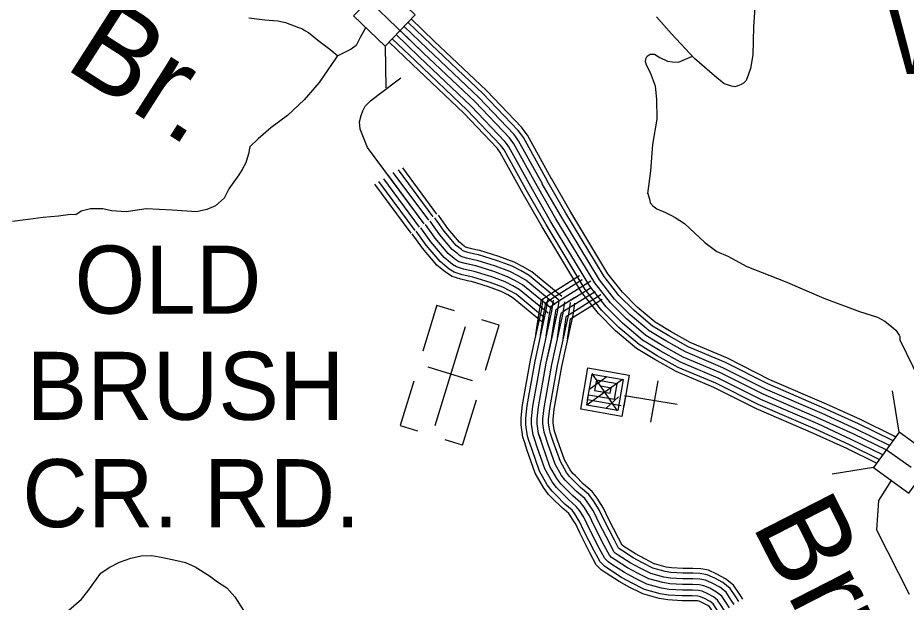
# Model space of a CAD drawing. Extents: x 1551132 to 1791609, y 378168 to 563823.
# Drawn here: x 1684674 to 1689511, y 423787 to 426966 of the extents above; entities that cross this region are included whole.
import ezdxf

# ---------------------------------------------------------------- set-up
doc = ezdxf.new("R2010")
doc.units = 0
for name, color, linetype in [('DESIGN - DRAINAGE - Bridges and Cross Drains Size Text', 7, 'Continuous'), ('DESIGN - ROW - Right-of-Way and Easement Labels', 7, 'Continuous'), ('DESIGN - TRANSPORTATION - Text', 7, 'Continuous'), ('DESIGN - UTILITIES - Cable (Underground) with Text', 7, 'Continuous'), ('SURVEY - CONTOURS - Index with Text', 7, 'Continuous'), ('SURVEY - DRAINAGE - Storm Sewer', 7, 'Continuous'), ('SURVEY - PROPERTY - Owners', 7, 'Continuous'), ('SURVEY - TRANSPORTATION - Roads', 7, 'Continuous')]:
    doc.layers.add(name, color=color, linetype=linetype)

msp = doc.modelspace()

# ---------------------------------------------------------------- linework, layer by layer
at = {"layer": 'DESIGN - TRANSPORTATION - Text'}
for points in [[(1688693.47, 427129.736), (1688679.112, 426917.664), (1688675.42, 426765.535), (1688662.579, 426689.599), (1688652.246, 426659.69), (1688639.863, 426625.798), (1688625.688, 426609.947), (1688611.622, 426604.106), (1688593.53, 426596.314), (1688591.505, 426594.339), (1688577.464, 426590.497), (1688559.506, 426594.714), (1688543.557, 426598.914), (1688519.64, 426607.206), (1688468.108, 426649.865), (1688359.161, 426745.259), (1688232.631, 426878.913), (1688151.658, 426971.982)], [(1685931.326, 426966.297), (1686019.216, 426955.239), (1686089.173, 426950.405), (1686131.055, 426939.896), (1686202.77, 426913.012), (1686220.719, 426908.796), (1686236.586, 426896.595), (1686256.477, 426886.345), (1686313.967, 426839.611), (1686373.474, 426794.859), (1686416.29, 426759.917)], [(1686567.728, 426912.863), (1686564.761, 426908.721), (1686538.204, 426858.978), (1686515.721, 426815.193), (1686489.496, 426795.485), (1686445.247, 426773.984), (1686413.073, 426758.35), (1686400.873, 426740.475), (1686362.224, 426682.865), (1686315.45, 426613.338), (1686232.402, 426520.219), (1686141.446, 426435.2), (1686050.69, 426368.198), (1685982, 426306.946)], [(1688104.158, 426008.531), (1688120.325, 426133.401), (1688131.933, 426277.422), (1688155.466, 426415.3), (1688152.666, 426523.462), (1688145.449, 426593.622), (1688118.25, 426666.032), (1688098.675, 426704.3), (1688090.917, 426726.417), (1688093.092, 426742.409), (1688101.275, 426758.334), (1688117.383, 426768.151), (1688141.383, 426767.868), (1688169.182, 426749.517), (1688210.981, 426731), (1688238.939, 426726.667), (1688270.913, 426724.284), (1688348.236, 426756.801)], [(1685982, 426306.946), (1685937.517, 426263.42), (1685929.093, 426225.478), (1685914.56, 426177.601), (1685896.16, 426141.775), (1685877.827, 426111.958), (1685823.187, 426036.256)], [(1685823.187, 426036.256), (1685796.571, 425984.513), (1685749.638, 425942.937), (1685702.464, 425924.061), (1685645.849, 425909.903), (1685513.769, 425919.344), (1685372.247, 425926.411), (1685263.75, 425909.902), (1685183.552, 425916.978), (1685136.378, 425926.411), (1685070.338, 425926.411), (1685018.439, 425914.627), (1684989.248, 425894.352), (1684961.265, 425896.702), (1684895.133, 425887.502), (1684811.027, 425880.535), (1684730.871, 425869.509), (1684644.714, 425858.559)], [(1688103.658, 426010.098), (1688113.308, 425979.939), (1688117.075, 425959.863), (1688130.891, 425943.671), (1688152.707, 425927.379), (1688200.481, 425906.77), (1688230.33, 425892.378), (1688252.188, 425880.095), (1688303.828, 425847.411), (1688414.659, 425743.908), (1688480.116, 425695.04), (1688539.848, 425670.273), (1688643.212, 425612.921), (1688852.349, 425532.236), (1689063.36, 425441.517), (1689256.581, 425369.04), (1689354.254, 425337.789), (1689394.003, 425315.272), (1689433.66, 425284.746), (1689455.46, 425266.454), (1689473.159, 425240.195), (1689477.067, 425232.137), (1689476.859, 425214.119), (1689585.573, 424991.18)], [(1689430.693, 424449.016), (1689429.168, 424450.258), (1689360.153, 424340.438), (1689349.728, 424181.092), (1689528.007, 423831.925)], [(1684952.198, 423743.995), (1685020.913, 423803.23), (1685055.429, 423846.856), (1685126.61, 423946.109), (1685170.968, 423975.602), (1685227.333, 424004.944), (1685289.598, 424026.203), (1685345.772, 424039.528), (1685403.812, 424040.82), (1685463.702, 424030.061), (1685539.559, 424015.111), (1685587.425, 424002.502), (1685639.182, 423979.835), (1685716.638, 423930.817), (1685760.27, 423898.233), (1685811.911, 423865.557), (1685855.36, 423816.956), (1685902.5, 423742.279)]]:
    msp.add_lwpolyline(points, dxfattribs=at)
at = {"layer": 'DESIGN - UTILITIES - Cable (Underground) with Text'}
for p, q in [((1686955.396, 425402.2), (1686879.234, 425152.669)), ((1687050.79, 425372.985), (1686956.013, 425402.025)), ((1687295.171, 425294.188), (1687199.735, 425323.27)), ((1687220.066, 425048.658), (1687295.087, 425294.138)), ((1687150.374, 424992.114), (1686907.836, 425066.21)), ((1686829.253, 424989.166), (1686755.731, 424748.702)), ((1688121.11, 424767.269), (1688160.665, 424992.015)), ((1687095.289, 424640.774), (1687170.702, 424887.704)), ((1686755.915, 424748.702), (1686849.85, 424719.92)), ((1687095.156, 424640.815), (1686999.987, 424669.856))]:
    msp.add_line(p, q, dxfattribs=at)
for points in [[(1687108.826, 425284.768), (1686944.234, 424746.372)], [(1687987.97, 424908.682), (1687983.087, 424909.648), (1687963.105, 424797.184), (1687738.534, 424836.78), (1687778.264, 425061.485), (1688002.835, 425021.888), (1687973.096, 424853.374), (1687969.137, 424854.249)], [(1687959.146, 424855.924), (1687776.599, 424887.996), (1687801.364, 425028.527), (1687969.836, 424998.655), (1687940.055, 424830.274), (1687771.708, 424859.88), (1687781.524, 424916.071), (1687921.88, 424891.39), (1687936.753, 424975.555), (1687824.506, 424995.403), (1687814.431, 424939.254), (1687898.696, 424924.43), (1687903.704, 424952.505), (1687847.522, 424962.446)], [(1687966.761, 424998.53), (1687773.825, 424860.805)], [(1687880.604, 425013.662), (1687788.999, 424946.954)], [(1687939.788, 424828.558), (1687800.664, 425030.644)], [(1687944.321, 424904.765), (1687877.131, 424842.457)], [(1688263.581, 424862.527), (1687977.278, 424910.532)]]:
    msp.add_lwpolyline(points, dxfattribs=at)
at = {"layer": 'SURVEY - CONTOURS - Index with Text'}
for points in [[(1687502.781, 426047.807), (1687374.109, 426280.796), (1687359.976, 426300.164), (1687350.301, 426313.564), (1687163.505, 426508.177), (1686881.071, 426776.409), (1686594.669, 427050.675), (1686288.393, 427345.099), (1686103.389, 427516.553), (1685954.168, 427649.723), (1685854.595, 427724.475), (1685673.141, 427821.803), (1685535.428, 427874.787), (1685401.639, 427915.722), (1685253.759, 427942.722), (1684941.967, 427992.84), (1684604.15, 428039.116), (1683694.396, 428125.201), (1683124.384, 428152.977), (1682908.423, 428170.419), (1682708.627, 428213.787), (1682458.833, 428259.488), (1682121.15, 428327.798)], [(1687557.054, 426077.783), (1687426.491, 426314.189), (1687410.15, 426336.59), (1687398.033, 426353.373), (1687207.238, 426552.145), (1686923.861, 426821.277), (1686798.514, 426941.314)], [(1687579.562, 426090.217), (1687448.224, 426328.039), (1687430.957, 426351.69), (1687417.824, 426369.882), (1687225.379, 426570.387), (1686941.603, 426839.894), (1686816.381, 426959.814)], [(1687475.648, 426032.823), (1687347.918, 426264.096), (1687334.893, 426281.955), (1687326.435, 426293.663), (1687141.639, 426486.193), (1686859.679, 426753.975), (1686733.916, 426874.412)], [(1687502.781, 426047.807), (1687374.109, 426280.796), (1687359.976, 426300.164), (1687350.301, 426313.564), (1687163.505, 426508.177), (1686881.071, 426776.409), (1686755.457, 426896.704)], [(1687529.913, 426062.791), (1687400.3, 426297.497), (1687385.059, 426318.372), (1687374.167, 426333.465), (1687185.372, 426530.161), (1686902.462, 426798.843), (1686776.973, 426919.013)], [(1687426.874, 426005.881), (1687300.844, 426234.087), (1687289.802, 426249.221), (1687283.544, 426257.887), (1687102.34, 426446.676), (1686821.23, 426713.649), (1686695.2, 426834.344)], [(1687448.507, 426017.831), (1687321.727, 426247.404), (1687309.802, 426263.738), (1687302.569, 426273.755), (1687119.773, 426464.209), (1686838.28, 426731.541), (1686712.375, 426852.111)], [(1689420.035, 424639.996), (1689416.793, 424642.246), (1689238.581, 424729.265), (1689054.135, 424813.442), (1688745.001, 424946.362), (1688513.307, 425062.79), (1688310.128, 425148.592), (1688202.356, 425208.635), (1688111.174, 425264.045), (1688008.493, 425350.831), (1687923.312, 425435.558), (1687840.389, 425541.586), (1687630.153, 425888.311), (1687529.663, 426063.249)], [(1689438.276, 424665.063), (1689432.518, 424669.063), (1689251.814, 424757.299), (1689066.693, 424841.793), (1688758.092, 424974.471), (1688526.315, 425090.949), (1688323.736, 425176.501), (1688217.955, 425235.428), (1688129.341, 425289.287), (1688029.468, 425373.698), (1687946.537, 425456.175), (1687865.947, 425559.228), (1687656.844, 425904.07), (1687556.538, 426078.691)], [(1689453.376, 424685.889), (1689445.568, 424691.314), (1689262.797, 424780.558), (1689077.11, 424865.302), (1688768.959, 424997.797), (1688537.098, 425114.316), (1688335.027, 425199.644), (1688230.888, 425257.662), (1688144.407, 425310.221), (1688046.859, 425392.665), (1687965.811, 425473.284), (1687887.138, 425573.87), (1687678.993, 425917.145), (1687578.837, 426091.5)], [(1689350.02, 424543.852), (1689188.307, 424622.812), (1689006.445, 424705.814), (1688695.285, 424839.601), (1688463.933, 424955.854), (1688258.429, 425042.639), (1688143.124, 425106.874), (1688042.193, 425168.218), (1687928.87, 425263.995), (1687835.098, 425357.264), (1687743.358, 425474.567), (1687528.772, 425828.468), (1687427.591, 426004.614)], [(1689364.536, 424564.269), (1689198.865, 424645.163), (1689016.461, 424728.407), (1688705.727, 424862.018), (1688474.299, 424978.313), (1688269.287, 425064.882), (1688155.557, 425128.242), (1688056.676, 425188.335), (1687945.587, 425282.229), (1687853.622, 425373.706), (1687763.733, 425488.643), (1687550.063, 425841.035), (1687449.024, 426016.923)], [(1689383.361, 424589.57), (1689212.098, 424673.197), (1689029.019, 424756.757), (1688718.818, 424890.127), (1688487.307, 425006.472), (1688282.895, 425092.791), (1688171.156, 425155.034), (1688074.842, 425213.577), (1687966.561, 425305.096), (1687876.847, 425394.323), (1687789.29, 425506.285), (1687576.754, 425856.794), (1687475.898, 426032.365)], [(1689538.574, 424519.968), (1689401.061, 424615.429), (1689225.34, 424701.231), (1689041.577, 424785.1), (1688731.91, 424918.245), (1688500.307, 425034.631), (1688296.512, 425120.691), (1688186.756, 425181.835), (1688093.008, 425238.811), (1687987.527, 425327.963), (1687900.079, 425414.941), (1687814.84, 425523.935), (1687603.453, 425872.553), (1687502.781, 426047.807)], [(1689401.81, 424614.912), (1689401.061, 424615.429), (1689225.34, 424701.231), (1689041.577, 424785.1), (1688731.91, 424918.245), (1688500.307, 425034.631), (1688296.512, 425120.691), (1688186.756, 425181.835), (1688093.008, 425238.811), (1687987.527, 425327.963), (1687900.079, 425414.941), (1687814.84, 425523.935), (1687603.453, 425872.553), (1687502.781, 426047.807)]]:
    msp.add_lwpolyline(points, dxfattribs=at)
at = {"layer": 'SURVEY - DRAINAGE - Storm Sewer'}
for p, q in [((1686673.13, 426811.539), (1686677.094, 426584.455)), ((1689472.637, 424712.36), (1689437.107, 424936.701)), ((1689332.983, 424520.139), (1689108.659, 424484.559))]:
    msp.add_line(p, q, dxfattribs=at)
for points in [[(1686502.242, 426976.552), (1686673.163, 426811.497), (1686838.226, 426982.435), (1686667.28, 427147.49)], [(1689525.196, 424380.486), (1689664.858, 424572.698), (1689472.637, 424712.36), (1689332.983, 424520.139)]]:
    msp.add_lwpolyline(points, close=True, dxfattribs=at)
at = {"layer": 'SURVEY - PROPERTY - Owners'}
msp.add_lwpolyline([(1688532.372, 423781.748), (1688506.764, 423820.107), (1688478.982, 423842.466), (1688441.166, 423862.934), (1688409.292, 423877.334), (1688383.317, 423881.642), (1688347.751, 423883.217), (1688293.761, 423883.217), (1688223.238, 423887.517), (1688185.272, 423893.968), (1688109.032, 423914.485), (1688047.234, 423945.769), (1687992.843, 423975.061), (1687925.72, 424018.246), (1687907.254, 424031.038), (1687894.612, 424043.588), (1687867.155, 424095.989), (1687812.248, 424202.792), (1687786.815, 424257.177), (1687757.282, 424303.586), (1687737.549, 424329.862), (1687695.175, 424366.138), (1687648.36, 424413.031), (1687630.544, 424431.265), (1687608.827, 424459.557), (1687571.503, 424526.101), (1687530.704, 424640.754), (1687509.622, 424705.33), (1687501.93, 424757.265), (1687502.23, 424785.307), (1687508.922, 424849.326), (1687551.512, 425087.199), (1687612.553, 425364.914), (1687621.428, 425425.807)], dxfattribs=at)
at = {"layer": 'SURVEY - TRANSPORTATION - Roads'}
for points in [[(1686886.47, 425846.268), (1686578.644, 426261.029), (1686537.753, 426359.556), (1686534.195, 426399.616), (1686542.57, 426435.542), (1686552.82, 426459.442), (1686565.086, 426485.318), (1686593.377, 426515.011), (1686633.66, 426544.57), (1686759.282, 426640.472)], [(1686956.102, 425897.953), (1686769.34, 426149.593)], [(1686886.47, 425846.268), (1686691.8, 426108.567)], [(1686911.361, 425864.744), (1686718.016, 426125.259)], [(1686936.252, 425883.219), (1686746.732, 426138.576)], [(1686816.038, 425793.992), (1686617.543, 426061.44)], [(1686836.688, 425809.317), (1686638.643, 426076.157)], [(1686861.579, 425827.793), (1686666.825, 426090.199)], [(1687155.647, 425650.421), (1687116.981, 425658.888), (1687088.349, 425667.68), (1687077.54, 425674.605), (1687069.107, 425681.522), (1687039.441, 425706.198), (1686970.876, 425786.117), (1686918.453, 425859.71)], [(1687162.28, 425680.706), (1687124.864, 425688.897), (1687101.498, 425696.064), (1687095.798, 425699.723), (1687088.849, 425705.423), (1687061.274, 425728.365), (1686995.317, 425805.242), (1686943.702, 425877.702)], [(1687167.572, 425704.848), (1687131.139, 425712.831), (1687111.99, 425718.707), (1687110.356, 425719.757), (1687104.59, 425724.482), (1687078.674, 425746.032), (1687014.8, 425820.493), (1686963.827, 425892.044)], [(1687142.381, 425589.853), (1687101.232, 425598.87), (1687062.032, 425610.895), (1687041.025, 425624.371), (1687029.625, 425633.721), (1686995.792, 425661.863), (1686922.011, 425747.866), (1686867.954, 425823.743)], [(1687580.895, 425382.998), (1687422.149, 425513.051), (1687383.692, 425535.902), (1687340.559, 425558.069), (1687265.253, 425585.995), (1687167.022, 425616.187), (1687109.106, 425628.879), (1687075.19, 425639.288), (1687059.283, 425649.488), (1687049.366, 425657.622), (1687017.617, 425684.031), (1686946.444, 425766.991), (1686893.203, 425841.726)], [(1687149.014, 425620.137), (1687109.106, 425628.879), (1687075.19, 425639.288), (1687059.283, 425649.488), (1687049.366, 425657.622), (1687017.617, 425684.031), (1686946.444, 425766.991), (1686893.203, 425841.726)], [(1687130.247, 425534.452), (1687086.815, 425543.96), (1687037.966, 425558.952), (1687007.625, 425578.411), (1686993.509, 425589.986), (1686955.852, 425621.312), (1686877.295, 425712.873), (1686821.763, 425790.825)], [(1687135.747, 425559.569), (1687093.348, 425568.861), (1687048.883, 425582.511), (1687022.767, 425599.253), (1687009.884, 425609.82), (1686973.96, 425639.696), (1686897.57, 425728.74), (1686842.704, 425805.75)], [(1687620.186, 425430.958), (1687457.831, 425563.969), (1687413.724, 425590.178), (1687365.592, 425614.912), (1687285.152, 425644.738), (1687182.788, 425676.206), (1687162.272, 425680.706)], [(1687635.844, 425450.083), (1687472.056, 425584.27), (1687425.699, 425611.812), (1687375.575, 425637.571), (1687293.085, 425668.164), (1687189.08, 425700.131), (1687167.563, 425704.848)], [(1687580.895, 425382.998), (1687422.149, 425513.051), (1687383.692, 425535.902), (1687340.559, 425558.069), (1687265.253, 425585.995), (1687167.022, 425616.187), (1687148.997, 425620.137)], [(1687600.536, 425406.982), (1687439.99, 425538.51), (1687398.708, 425563.036), (1687353.076, 425586.487), (1687275.202, 425615.371), (1687174.905, 425646.196), (1687155.63, 425650.421)], [(1687561.254, 425359.014), (1687404.308, 425487.592), (1687368.675, 425508.768), (1687328.043, 425529.652), (1687255.303, 425556.619), (1687159.138, 425586.178), (1687142.364, 425589.853)], [(1687525.313, 425315.138), (1687371.667, 425441.008), (1687341.201, 425459.117), (1687305.135, 425477.65), (1687237.095, 425502.884), (1687144.714, 425531.277), (1687130.222, 425534.452)], [(1687541.604, 425335.038), (1687386.466, 425462.133), (1687353.659, 425481.625), (1687315.526, 425501.226), (1687245.353, 425527.252), (1687151.255, 425556.169), (1687135.722, 425559.569)], [(1687495.047, 425243.553), (1687512.43, 425362.856), (1687526.013, 425431.249), (1687578.837, 425468.792), (1687731.658, 425563.769)], [(1687520.497, 425239.844), (1687537.78, 425358.497), (1687549.246, 425416.216), (1687593.078, 425447.375), (1687747.1, 425543.077)], [(1687551.171, 425235.369), (1687568.345, 425353.239), (1687577.245, 425398.082), (1687610.261, 425421.549), (1687794.507, 425536.052)], [(1687581.845, 425230.902), (1687598.903, 425347.98), (1687605.253, 425379.956), (1687627.436, 425395.723), (1687794.907, 425499.801)], [(1687612.519, 425226.436), (1687629.461, 425342.722), (1687633.261, 425361.831), (1687644.61, 425369.898), (1687817.998, 425477.651)], [(1687485.864, 425197.11), (1687526.205, 425380.673), (1687534.63, 425438.458)], [(1688532.372, 423781.748), (1688506.764, 423820.107), (1688478.982, 423842.466), (1688441.166, 423862.934), (1688409.292, 423877.334), (1688383.317, 423881.642), (1688347.751, 423883.217), (1688293.761, 423883.217), (1688223.238, 423887.517), (1688185.272, 423893.968), (1688109.032, 423914.485), (1688047.234, 423945.769), (1687992.843, 423975.061), (1687925.72, 424018.246), (1687907.254, 424031.038), (1687894.612, 424043.588), (1687867.155, 424095.989), (1687812.248, 424202.792), (1687786.815, 424257.177), (1687757.282, 424303.586), (1687737.549, 424329.862), (1687695.175, 424366.138), (1687648.36, 424413.031), (1687630.544, 424431.265), (1687608.827, 424459.557), (1687571.503, 424526.101), (1687530.704, 424640.754), (1687509.622, 424705.33), (1687501.93, 424757.265), (1687502.23, 424785.307), (1687508.922, 424849.326), (1687551.512, 425087.199), (1687612.553, 425364.914), (1687621.428, 425425.807)], [(1687510.98, 425191.593), (1687551.521, 425376.056), (1687560.079, 425434.749)], [(1687541.263, 425184.943), (1687582.037, 425370.481), (1687590.753, 425430.283)], [(1687571.537, 425178.284), (1687612.553, 425364.914), (1687621.428, 425425.807)], [(1687581.845, 425230.902), (1687598.903, 425347.98), (1687605.253, 425379.956), (1687627.436, 425395.723), (1687705.426, 425444.191)], [(1687601.811, 425171.626), (1687643.069, 425359.347), (1687652.102, 425421.332)], [(1687643.194, 425221.96), (1687660.027, 425337.464), (1687661.26, 425343.697), (1687661.793, 425344.072), (1687848.839, 425460.333)], [(1687667.651, 425218.402), (1687683.709, 425328.597), (1687855.889, 425435.616)], [(1687632.094, 425164.976), (1687673.585, 425353.772), (1687682.776, 425416.866)], [(1687656.227, 425159.667), (1687697.909, 425349.331), (1687707.234, 425413.299)], [(1687432.498, 424658.937), (1687423.94, 424685.146), (1687414.149, 424751.273), (1687414.565, 424790.349), (1687422.015, 424861.634), (1687465.473, 425104.349), (1687485.864, 425197.135)], [(1687456.939, 424666.921), (1687449.056, 424691.063), (1687439.882, 424753.031), (1687440.265, 424788.866), (1687447.498, 424858.026), (1687490.697, 425099.324), (1687510.98, 425191.61)], [(1687486.414, 424676.538), (1687479.339, 424698.197), (1687470.906, 424755.148), (1687471.247, 424787.091), (1687478.206, 424853.676), (1687521.105, 425093.257), (1687541.263, 425184.959)], [(1687515.88, 424686.163), (1687509.622, 424705.33), (1687501.93, 424757.265), (1687502.23, 424785.307), (1687508.922, 424849.326), (1687551.512, 425087.199), (1687571.537, 425178.301)], [(1687545.346, 424695.788), (1687539.904, 424712.464), (1687532.954, 424759.382), (1687533.213, 424783.524), (1687539.638, 424844.976), (1687581.92, 425081.14), (1687601.811, 425171.642)], [(1687574.82, 424705.405), (1687570.187, 424719.597), (1687563.979, 424761.498), (1687564.195, 424781.749), (1687570.345, 424840.625), (1687612.328, 425075.073), (1687632.094, 425164.992)], [(1687598.311, 424713.08), (1687594.328, 424725.281), (1687588.711, 424763.19), (1687588.895, 424780.324), (1687594.836, 424837.159), (1687636.569, 425070.24), (1687656.227, 425159.684)], [(1687803.923, 424288.028), (1687782.79, 424321.245), (1687760.29, 424351.196), (1687716.258, 424388.897), (1687670.418, 424434.815), (1687654.01, 424451.607), (1687634.777, 424476.666), (1687599.828, 424538.976), (1687560.045, 424650.762), (1687545.337, 424695.805)], [(1687830.08, 424304.67), (1687808.298, 424338.904), (1687783.04, 424372.538), (1687737.333, 424411.664), (1687692.467, 424456.599), (1687677.476, 424471.949), (1687660.718, 424493.775), (1687628.152, 424551.843), (1687589.386, 424660.771), (1687574.803, 424705.422)], [(1687850.93, 424317.945), (1687828.639, 424352.979), (1687801.173, 424389.547), (1687754.141, 424429.806), (1687710.058, 424473.974), (1687696.184, 424488.175), (1687681.409, 424507.417), (1687650.735, 424562.11), (1687612.786, 424668.754), (1687598.303, 424713.097)], [(1687703.775, 424224.293), (1687685.109, 424253.627), (1687673.192, 424269.485), (1687635.527, 424301.736), (1687585.953, 424351.388), (1687564.153, 424373.705), (1687535.412, 424411.147), (1687491.364, 424489.675), (1687447.681, 424612.428), (1687432.49, 424658.954)], [(1687725.466, 424238.101), (1687706.267, 424268.269), (1687692.059, 424287.186), (1687653.018, 424320.612), (1687604.252, 424369.463), (1687583.611, 424390.58), (1687556.937, 424425.34), (1687514.855, 424500.358), (1687472.022, 424620.736), (1687456.939, 424666.937)], [(1687751.624, 424254.743), (1687731.774, 424285.928), (1687714.808, 424308.528), (1687674.092, 424343.379), (1687626.302, 424391.247), (1687607.077, 424410.923), (1687582.878, 424442.448), (1687543.179, 424513.225), (1687501.363, 424630.745), (1687486.405, 424676.554)], [(1687777.773, 424271.386), (1687757.282, 424303.586), (1687737.549, 424329.862), (1687695.175, 424366.138), (1687648.36, 424413.031), (1687630.544, 424431.265), (1687608.827, 424459.557), (1687571.503, 424526.101), (1687530.704, 424640.754), (1687515.871, 424686.18)], [(1688141.706, 423995.137), (1688087.383, 424022.638), (1688036.926, 424049.813), (1687973.877, 424090.373), (1687964.644, 424096.773), (1687944.119, 424135.94), (1687890.112, 424241.002), (1687862.988, 424298.995), (1687850.93, 424317.954)], [(1688102.541, 423917.768), (1688047.234, 423945.769), (1687992.843, 423975.061), (1687925.72, 424018.246), (1687907.254, 424031.038), (1687894.612, 424043.588), (1687867.155, 424095.989), (1687812.248, 424202.792), (1687786.815, 424257.177), (1687777.765, 424271.402)], [(1688116.54, 423945.427), (1688061.583, 423973.253), (1688008.601, 424001.787), (1687942.936, 424044.03), (1687927.153, 424054.963), (1687919.845, 424062.214), (1687894.671, 424110.273), (1687840.08, 424216.451), (1687814.048, 424272.127), (1687803.923, 424288.044)], [(1688130.54, 423973.086), (1688075.941, 424000.729), (1688024.359, 424028.504), (1687960.152, 424069.814), (1687947.053, 424078.889), (1687945.086, 424080.847), (1687922.178, 424124.557), (1687867.913, 424230.11), (1687841.28, 424287.078), (1687830.072, 424304.686)], [(1688062.925, 423839.508), (1688006.626, 423868.008), (1687948.253, 423899.443), (1687877.004, 423945.285), (1687850.947, 423963.336), (1687823.206, 423990.878), (1687789.298, 424055.58), (1687733.491, 424164.141), (1687709.767, 424214.876), (1687703.758, 424224.318)], [(1688074.541, 423862.45), (1688018.526, 423890.809), (1687961.327, 423921.618), (1687891.287, 423966.678), (1687867.454, 423983.186), (1687844.138, 424006.329), (1687812.131, 424067.422), (1687756.582, 424175.475), (1687732.349, 424227.276), (1687725.458, 424238.118)], [(1688088.541, 423890.109), (1688032.884, 423918.285), (1687977.085, 423948.336), (1687908.504, 423992.462), (1687887.354, 424007.112), (1687869.379, 424024.963), (1687839.638, 424081.706), (1687784.415, 424189.133), (1687759.582, 424242.226), (1687751.607, 424254.76)], [(1688600.096, 423791.348), (1688584.138, 423815.874), (1688553.047, 423862.442), (1688513.456, 423894.309), (1688468.715, 423918.518), (1688427.433, 423937.177), (1688389.784, 423943.419), (1688349.126, 423945.219), (1688295.653, 423945.219), (1688230.338, 423949.202), (1688198.547, 423954.602), (1688131.315, 423972.695), (1688130.507, 423973.103)], [(1688620.812, 423804.832), (1688604.779, 423829.474), (1688571.496, 423879.326), (1688527.197, 423914.977), (1688479.707, 423940.677), (1688434.666, 423961.028), (1688392.359, 423968.045), (1688349.668, 423969.936), (1688296.403, 423969.936), (1688233.171, 423973.795), (1688203.838, 423978.778), (1688140.198, 423995.904)], [(1688574.113, 423774.44), (1688558.255, 423798.807), (1688529.906, 423841.275), (1688496.215, 423868.384), (1688454.941, 423890.726), (1688418.358, 423907.251), (1688386.551, 423912.526), (1688348.435, 423914.218), (1688294.703, 423914.218), (1688226.788, 423918.36), (1688191.913, 423924.285), (1688120.174, 423943.594), (1688116.515, 423945.444)], [(1688522.147, 423740.622), (1688506.489, 423764.689), (1688483.623, 423798.94), (1688461.749, 423816.549), (1688427.391, 423835.141), (1688400.225, 423847.416), (1688380.084, 423850.758), (1688347.068, 423852.217), (1688292.819, 423852.217), (1688219.688, 423856.675), (1688178.63, 423863.65), (1688097.891, 423885.376), (1688088.533, 423890.109)], [(1688548.13, 423757.531), (1688532.372, 423781.748), (1688506.764, 423820.107), (1688478.982, 423842.466), (1688441.166, 423862.934), (1688409.292, 423877.334), (1688383.317, 423881.642), (1688347.751, 423883.217), (1688293.761, 423883.217), (1688223.238, 423887.517), (1688185.272, 423893.968), (1688109.032, 423914.485), (1688102.524, 423917.776)], [(1688474.607, 423709.688), (1688459.132, 423733.472), (1688441.283, 423760.206), (1688430.208, 423769.123), (1688402.184, 423784.29), (1688383.626, 423792.673), (1688374.168, 423794.24), (1688345.81, 423795.498), (1688291.086, 423795.498), (1688213.196, 423800.248), (1688166.489, 423808.182), (1688077.508, 423832.124), (1688062.933, 423839.499)], [(1688496.165, 423723.713), (1688480.607, 423747.622), (1688460.482, 423777.773), (1688444.508, 423790.623), (1688413.617, 423807.349), (1688391.15, 423817.491), (1688376.851, 423819.866), (1688346.376, 423821.216), (1688291.869, 423821.216), (1688216.138, 423825.832), (1688171.997, 423833.333), (1688086.749, 423856.275), (1688074.541, 423862.45)]]:
    msp.add_lwpolyline(points, dxfattribs=at)

# ---------------------------------------------------------------- texts
at = {"layer": 'DESIGN - DRAINAGE - Bridges and Cross Drains Size Text'}
for s, height, rotation, p in [('Br.', 474.9955, 327.384956, (1684919.146, 426697.785)), ('Brush', 475.0074, 297.048089, (1688666.686, 424210.676))]:
    msp.add_text(s, height=height, rotation=rotation, dxfattribs=at).set_placement(p)
at = {"layer": 'DESIGN - ROW - Right-of-Way and Easement Labels'}
for s, rotation, p in [('WINDING', 0.253917, (1689412.836, 426659.291)), ('OLD', 0.000028, (1684982.681, 425357.179)), ('BRUSH', 0.000028, (1684720.854, 424779.347)), ('CR. RD.', 0.000028, (1684697.795, 424195.54))]:
    msp.add_text(s, height=369.9913, rotation=rotation, dxfattribs=at).set_placement(p)

doc.saveas('drawing.dxf')
